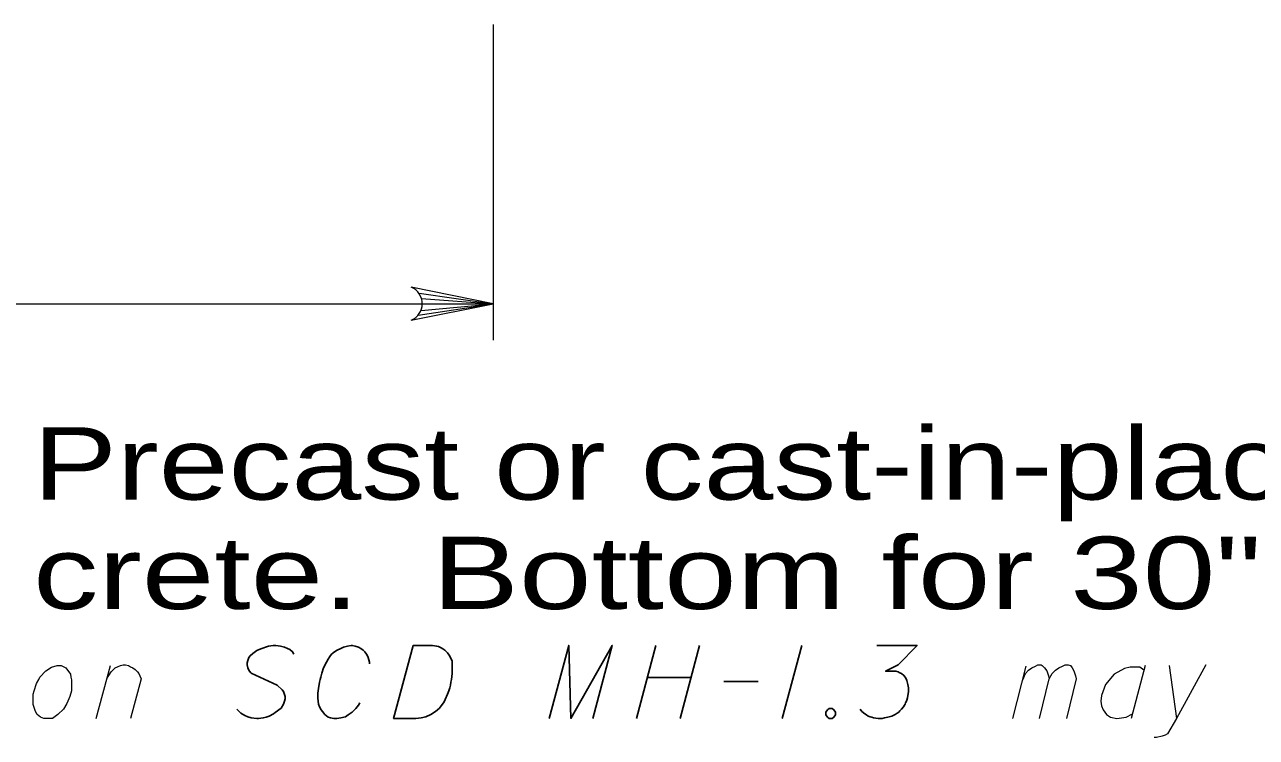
# Model space of a CAD drawing. Extents: x 1083.1 to 1117.1, y 697.4 to 741.4.
# Drawn here: x 1091.69 to 1094.348, y 727.862 to 729.4 of the extents above; entities that cross this region are included whole.
import ezdxf

# ---------------------------------------------------------------- set-up
doc = ezdxf.new("R2010")
doc.units = 0
doc.header["$LTSCALE"] = 0.062
doc.layers.add('1', color=7, linetype='Continuous', lineweight=13)

msp = doc.modelspace()

# ---------------------------------------------------------------- linework, layer by layer
at = {"layer": '1'}
for p, q in [((1092.70133, 729.39967), (1092.70133, 728.71908)), ((1092.54108, 728.82017), (1092.70133, 728.79775)), ((1092.5465, 728.80908), (1092.70133, 728.79775)), ((1091.5165, 728.79775), (1092.70133, 728.79775)), ((1092.53917, 728.77292), (1092.70133, 728.79775)), ((1092.54533, 728.78333), (1092.70133, 728.79775)), ((1092.54817, 728.79775), (1092.70133, 728.79775)), ((1091.84442, 727.90325), (1091.87542, 728.01725)), ((1093.82283, 727.90325), (1093.85133, 728.016)), ((1094.10783, 728.01725), (1094.07808, 727.90325)), ((1094.15983, 728.01725), (1094.17592, 727.90325)), ((1093.87983, 727.90325), (1093.90092, 727.98875))]:
    msp.add_line(p, q, dxfattribs=at)
at = {"layer": '1', "lineweight": 25}
for p, q in [((1093.05233, 728.06058), (1093.01017, 727.90325)), ((1093.14642, 728.06058), (1093.10433, 727.90325)), ((1093.367, 728.06058), (1093.32483, 727.90325)), ((1093.03375, 727.99125), (1093.12783, 727.99125)), ((1093.1985, 727.98258), (1093.27283, 727.98258))]:
    msp.add_line(p, q, dxfattribs=at)
at = {"layer": '1'}
for points in [[(1092.52433, 728.76233), (1092.70133, 728.79775), (1092.52433, 728.83317)], [(1091.868, 727.99), (1091.87167, 727.99617), (1091.87667, 728.00367), (1091.88033, 728.00733), (1091.88533, 728.01233), (1091.89025, 728.01475), (1091.8965, 728.01725), (1091.90267, 728.0185), (1091.90758, 728.0185), (1091.91383, 728.01725), (1091.91875, 728.01475), (1091.92375, 728.01233), (1091.92867, 728.00858), (1091.93367, 728.00367), (1091.93608, 727.99992), (1091.93858, 727.99492), (1091.94108, 727.98875), (1091.91875, 727.90325)], [(1093.84392, 727.98625), (1093.85008, 727.99992), (1093.85633, 728.00733), (1093.86375, 728.01233), (1093.87117, 728.016), (1093.87617, 728.0185), (1093.88358, 728.0185), (1093.88608, 728.01725), (1093.891, 728.01233), (1093.89592, 728.00608), (1093.89967, 727.99492), (1093.90092, 727.98875), (1093.90708, 727.99992), (1093.9145, 728.00733), (1093.922, 728.01233), (1093.92942, 728.016), (1093.93558, 728.0185), (1093.94183, 728.0185), (1093.94675, 728.01725), (1093.9505, 728.01233), (1093.95417, 728.00608), (1093.95792, 727.99492), (1093.95917, 727.98875), (1093.93808, 727.90325)], [(1094.10533, 728.00733), (1094.09667, 728.0135), (1094.07558, 728.0135), (1094.06317, 728.01108), (1094.04092, 727.99867), (1094.02233, 727.97633), (1094.01367, 727.95283), (1094.01242, 727.94042), (1094.01367, 727.9305), (1094.01733, 727.92183), (1094.02483, 727.91192), (1094.0335, 727.90575), (1094.04708, 727.90325), (1094.057, 727.9045), (1094.06692, 727.90575), (1094.08058, 727.91317)], [(1094.23908, 728.0185), (1094.17592, 727.90325), (1094.15608, 727.86983), (1094.15117, 727.86733), (1094.14492, 727.86492), (1094.13258, 727.86242), (1094.12758, 727.86242)]]:
    msp.add_lwpolyline(points, dxfattribs=at)
at = {"layer": '1', "lineweight": 25}
for points in [[(1092.27058, 728.042), (1092.26808, 728.047), (1092.26192, 728.05192), (1092.25692, 728.05442), (1092.25075, 728.05692), (1092.24208, 728.05942), (1092.23217, 728.06058), (1092.226, 728.06058), (1092.21608, 728.05942), (1092.2, 728.05317), (1092.19133, 728.0495), (1092.18258, 728.04325), (1092.17642, 728.03833), (1092.17392, 728.03458), (1092.1715, 728.02842), (1092.17025, 728.02342), (1092.17025, 728.0185), (1092.1715, 728.01233), (1092.17392, 728.00733), (1092.17767, 728.00242), (1092.17892, 728.00117), (1092.23467, 727.97517), (1092.24583, 727.96525), (1092.24825, 727.9615), (1092.2495, 727.959), (1092.252, 727.95033), (1092.252, 727.94542), (1092.25075, 727.94042), (1092.24825, 727.93425), (1092.24333, 727.92558), (1092.23092, 727.91567), (1092.22725, 727.91317), (1092.21733, 727.90825), (1092.21108, 727.90575), (1092.20492, 727.9045), (1092.195, 727.90325), (1092.19133, 727.90325), (1092.17892, 727.9045), (1092.1715, 727.907), (1092.16525, 727.9095), (1092.15658, 727.91442), (1092.14792, 727.92308)], [(1092.43408, 728.021), (1092.43408, 728.02467), (1092.43283, 728.02967), (1092.43167, 728.03458), (1092.42917, 728.03958), (1092.42792, 728.042), (1092.42417, 728.047), (1092.4205, 728.05067), (1092.4155, 728.05442), (1092.41058, 728.05692), (1092.40317, 728.05942), (1092.39692, 728.06058), (1092.3945, 728.06058), (1092.387, 728.05942), (1092.37833, 728.05692), (1092.37217, 728.05442), (1092.36475, 728.05067), (1092.3585, 728.047), (1092.35233, 728.042), (1092.34867, 728.03708), (1092.34492, 728.03092), (1092.34117, 728.02467), (1092.335, 728.01233), (1092.33125, 728.00117), (1092.32883, 727.9925), (1092.32758, 727.9875), (1092.32633, 727.98133), (1092.32383, 727.96767), (1092.32258, 727.95775), (1092.32258, 727.94667), (1092.32383, 727.93425), (1092.32633, 727.92808), (1092.33008, 727.92183), (1092.3325, 727.91817), (1092.3375, 727.91192), (1092.34492, 727.90575), (1092.34983, 727.9045), (1092.35733, 727.90325), (1092.36225, 727.90325), (1092.3635, 727.90325), (1092.37217, 727.9045), (1092.38208, 727.907), (1092.38825, 727.91075), (1092.39692, 727.91692), (1092.40442, 727.92433), (1092.41058, 727.93175), (1092.41308, 727.93675)], [(1092.82192, 727.90325), (1092.864, 728.06058), (1092.86892, 727.90325), (1092.95817, 728.06058), (1092.916, 727.90325)], [(1093.52925, 728.06058), (1093.616, 728.06058), (1093.57508, 728.0185), (1093.54783, 728.00483), (1093.57017, 728.00483), (1093.57508, 728.00367), (1093.57758, 728.00242), (1093.58, 728.00117), (1093.5825, 727.99992), (1093.5875, 727.99617), (1093.58992, 727.9925), (1093.59242, 727.98875), (1093.59367, 727.98508), (1093.59617, 727.97633), (1093.59742, 727.96892), (1093.59742, 727.96525), (1093.59742, 727.96025), (1093.59617, 727.95283), (1093.59492, 727.94792), (1093.59367, 727.94292), (1093.59242, 727.93925), (1093.59117, 727.93675), (1093.58992, 727.93425), (1093.58875, 727.93175), (1093.58625, 727.92808), (1093.5825, 727.92308), (1093.57883, 727.91942), (1093.57633, 727.91692), (1093.57258, 727.91442), (1093.56892, 727.91192), (1093.56392, 727.9095), (1093.5615, 727.90825), (1093.55275, 727.90575), (1093.54533, 727.9045), (1093.54042, 727.90325), (1093.53175, 727.90325), (1093.52183, 727.9045), (1093.51808, 727.90575), (1093.51442, 727.907), (1093.51067, 727.90825), (1093.50692, 727.91075), (1093.50325, 727.91317), (1093.497, 727.91817), (1093.49333, 727.92308)]]:
    msp.add_lwpolyline(points, dxfattribs=at)
for points in [[(1092.52825, 728.06058), (1092.57042, 728.06058), (1092.57908, 728.05942), (1092.58275, 728.05817), (1092.589, 728.05567), (1092.59267, 728.05317), (1092.59642, 728.05067), (1092.60258, 728.0445), (1092.60633, 728.03958), (1092.6125, 728.02717), (1092.6125, 727.99992), (1092.61125, 727.9875), (1092.61, 727.98133), (1092.60875, 727.97517), (1092.60758, 727.96892), (1092.60508, 727.96275), (1092.60258, 727.95533), (1092.59767, 727.94417), (1092.59517, 727.93925), (1092.58525, 727.92558), (1092.57658, 727.91817), (1092.56667, 727.91192), (1092.5555, 727.907), (1092.54558, 727.9045), (1092.53442, 727.90325), (1092.48617, 727.90325)], [(1093.42642, 727.92433), (1093.43267, 727.92433), (1093.43633, 727.92183), (1093.44008, 727.91692), (1093.44008, 727.91075), (1093.43633, 727.90575), (1093.43267, 727.90325), (1093.42642, 727.90325), (1093.42275, 727.90575), (1093.419, 727.91075), (1093.419, 727.91692), (1093.42275, 727.92183)]]:
    msp.add_lwpolyline(points, close=True, dxfattribs=at)
at = {"layer": '1'}
msp.add_lwpolyline([(1091.76017, 728.01725), (1091.76883, 728.01725), (1091.77875, 728.01233), (1091.78867, 727.99867), (1091.78992, 727.9925), (1091.79117, 727.98625), (1091.79117, 727.98133), (1091.79117, 727.96275), (1091.78742, 727.95033), (1091.78125, 727.9355), (1091.77383, 727.92308), (1091.76142, 727.91192), (1091.75025, 727.90325), (1091.73167, 727.90325), (1091.72425, 727.90575), (1091.71683, 727.91192), (1091.71308, 727.91817), (1091.70817, 727.933), (1091.70817, 727.95533), (1091.71067, 727.96275), (1091.71558, 727.97883), (1091.72058, 727.9875), (1091.723, 727.9925), (1091.73542, 728.00608), (1091.74783, 728.0135)], close=True, dxfattribs=at)
msp.add_arc((1092.51, 728.79776), 0.0382, 292.08605, 67.91218, dxfattribs=at)

# ---------------------------------------------------------------- texts
for s, width, p in [('Precast or cast-in-place con', 1.3, (1091.70817, 728.37525)), ('crete.  Bottom for 30" [760] sewer', 1.35, (1091.70817, 728.13925))]:
    msp.add_text(s, height=0.156, dxfattribs=dict(at, width=width)).set_placement(p)

doc.saveas('drawing.dxf')
